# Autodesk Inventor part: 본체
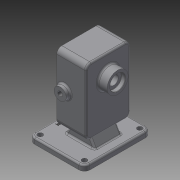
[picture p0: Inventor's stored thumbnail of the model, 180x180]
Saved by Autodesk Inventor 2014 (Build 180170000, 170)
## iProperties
Created: 2020-04
Part Number: 본체
Material: Generic
Document SubType Name: Modeling
Designer: kh
Density: 1 g/cm^3
Appearance: Default
Author: kh
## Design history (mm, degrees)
sketch "스케치1"
  geometry: L1 (-50, 60)-(50, 60); L2 (50, 60)-(50, -60); L3 (50, -60)-(-50, -60); L4 (-50, -60)-(-50, 60); L5 (-50, 60)-(50, -60); L6 (50, 60)-(-50, -60); 1 further point
  constraints: 12 end point, 2 midpoint, 2 parallel, 1 horizontal, 1 perpendicular
  dimensions: "d0" = 100 distance of L1.start L1.end; "d1" = 120 distance of L3.end L1.start
extrude "돌출1" new body sketch "스케치1" distance "d2" = 10; taper "d3" = 0 deg
node "작업 평면1"
sketch "스케치2"
  geometry: L1 (0, 60)-(-150, 60); L2 (-150, 20)-(-30, 20); L3 (-30, 20)-(-30, 100); L4 (-30, 100)-(-150, 100); L5 (-150, 100)-(-150, 20)
  constraints: 10 end point, 2 horizontal, 2 parallel, 1 midpoint, 1 perpendicular
  dimensions: "d5" = 150 distance of L1.end L1.start; "d6" = 80 distance of L4.end L2.start; "d7" = 120 distance of L2.start L2.end
extrude "돌출2" join sketch "스케치2" distance "d8" = 53; taper "d9" = 0 deg
sketch "스케치3"
  geometry: L1 (0, 60)-(90, 60); L2 (112, 60)-(68, 60); L3 (112, 84)-(68, 84); L4 (68, 36)-(112, 36); A1 r 24 centre (112, 60) between (112, 36) and (112, 84); A2 r 24 centre (68, 60) between (68, 84) and (68, 36); 1 further point
  constraints: 10 end point, 4 point on circle, 4 tangent, 2 centre point, 1 coincident, 1 collinear, 1 horizontal, 1 midpoint, 1 parallel
  dimensions: "d10" = 90 distance of L1.start L1.end; "d11" = 44 distance of L2.start L2.end; "d12" = 48 diameter of A2
extrude "돌출3" cut sketch "스케치3" distance "d13" = 29; taper "d14" = 0 deg
sketch "스케치4"
  geometry: L1 (68, 84)-(112, 84) reference; L2 (112, 36)-(68, 36) reference; C1 r 12.5 at (112, 60); C2 r 12.5 at (68, 60); A1 r 24 centre (68, 60) between (68, 84) and (68, 36) reference; A2 r 24 centre (112, 60) between (112, 36) and (112, 84) reference; 1 further point
  constraints: 2 centre point, 2 coincident
  dimensions: "d15" = 25 diameter of C1; "d16" = 25 diameter of C2
extrude "돌출4" cut sketch "스케치4" distance "d17" = 15; taper "d18" = 0 deg
chamfer "모따기1" distance "d19" = 1; stored, may be unused: second distance "d20" = 2, angle "d21" = 45 deg
sketch "스케치5"
  geometry: C1 r 12.5 at (-112, 60) reference; C2 r 19 at (-112, 60); 1 further point
  constraints: 1 centre point, 1 coincident
  dimensions: "d22" = 38 diameter of C2
extrude "돌출5" join sketch "스케치5" distance "d23" = 17; taper "d24" = 0 deg
sketch "스케치6"
  geometry: C1 r 19 at (0, 0) reference; C2 r 14 at (0, 0); 1 further point
  constraints: 1 centre point, 1 coincident
  dimensions: "d25" = 28 diameter of C2
extrude "돌출6" cut sketch "스케치6" distance "d26" = 7.3; taper "d27" = 0 deg
chamfer "모따기2" distance "d28" = 0.7; stored, may be unused: second distance "d29" = 2, angle "d30" = 30 deg
fillet "모깎기1" dims "d31" = 0.5
sketch "스케치7"
  geometry: C1 r 13.5 at (0, 0) reference; C2 r 8.5 at (0, 0); 1 further point
  constraints: 1 centre point, 1 coincident
  dimensions: "d32" = 17 diameter of C2
extrude "돌출7" cut sketch "스케치7" stored distance "d33" = 7.3; taper "d34" = 0 deg
sketch "스케치8"
  geometry: L1 (-53, 0)-(-53, 120) reference; L2 (17, -30)-(-83, -30) reference; C1 r 11 at (-39, 60); 2 further points
  constraints: 1 centre point, 1 coincident
  dimensions: "d35" = 14 distance from line of L1 point (-39, 60); "d36" = 90 distance from line of L2 point (-39, 60); "d37" = 22 diameter of C1
extrude "돌출8" join sketch "스케치8" distance "d38" = 8; taper "d39" = 0 deg
hole "구멍1" diameter "d42" = 8.917; stored, may be unused: countersink angle "d46" = 90 deg, drill point angle "d48" = 118 deg; dims "d40" = 10, "d41" = 10, "d43" = 6, "d44" = 4, "d45" = 2, "d47" = 8
fillet "모깎기2" dims "d49" = 10
fillet "모깎기3" dims "d50" = 9
fillet "모깎기4" dims "d51" = 3
sketch "스케치9"
  geometry: L1 (-50, -50)-(-50, 50) reference; L2 (-40, 60)-(40, 60) reference; L3 (50, 50)-(50, -50) reference; L4 (40, -60)-(-40, -60) reference; A1 r 10 centre (-40, -50) between (-50, -50) and (-40, -60) reference; A2 r 10 centre (-40, 50) between (-40, 60) and (-50, 50) reference; A3 r 10 centre (40, 50) between (50, 50) and (40, 60) reference; A4 r 10 centre (40, -50) between (40, -60) and (50, -50) reference; 1 further point
hole "구멍2" sketch "스케치9" at (-40, 50), (-40, -50), (40, -50), (40, 50) diameter "d52" = 9; stored, may be unused: countersink angle "d56" = 90 deg, drill point angle "d58" = 118 deg; dims "d53" = 6, "d54" = 4, "d55" = 2, "d57" = 8
sketch "스케치10"
  geometry: L1 (0, 60)-(90, 60); L2 (141, 91)-(39, 91); L3 (39, 91)-(39, 29); L4 (39, 29)-(141, 29); L5 (141, 29)-(141, 91); L6 (141, 91)-(39, 29); L7 (39, 91)-(141, 29); C1 r 8.5 at (112, 60) reference; C2 r 12.5 at (68, 60) reference; 8 further points
  constraints: 14 end point, 4 coincident, 4 point on line, 2 horizontal, 2 midpoint, 2 parallel, 2 symmetric about line, 1 perpendicular
  dimensions: "d59" = 90 distance of L1.start L1.end; "d60" = 62 distance of L4.end L2.start; "d61" = 102 distance of L3.end L4.end; "d62" = 44 distance of point (68, 29) point (112, 29); "d63" = 22 horizontal distance of L1.end point (112, 29)
hole "구멍3" sketch "스케치10" at (141, 91), (141, 29), (39, 29), (39, 91), (112, 91), (112, 29), (68, 91), (68, 29) diameter "d64" = 4.459; stored, may be unused: countersink angle "d68" = 90 deg, drill point angle "d70" = 118 deg; dims "d65" = 10, "d66" = 4, "d67" = 2, "d69" = 12
sketch "스케치11"
  geometry: L1 (-36.998, 20.739)-(-36.998, -20.739); L2 (-36.998, -20.739)-(-43.002, -20.739); L3 (-43.002, -20.739)-(-43.002, 20.739); L4 (-43.002, 20.739)-(-36.998, 20.739); L5 (-36.998, 20.739)-(-43.002, -20.739); L6 (-36.998, -20.739)-(-43.002, 20.739); L7 (-50, 50)-(-50, -50) reference; L8 (40, 60)-(-40, 60) reference; 2 further points
  constraints: 4 end point, 1 midpoint, 2 other
  dimensions: "d71" = 10 distance from line of point (-40, 0) L7; "d72" = 60 distance from line of point (-40, 0) L8
feature "엠보싱1" sketch "스케치11" dims "d0" = 100, "d1" = 120, "d10" = 90, "d11" = 44, "d12" = 48, "d73" = 0.5, "d74" = 0
sketch "스케치12"
  geometry: L1 (-33, 30)-(20, 30) reference; L2 (40, 10)-(-40, 10) reference; L3 (8.453, 30)-(20, 10); L4 (-21.453, 30)-(-33, 10); L5 (20, 150)-(-33, 150) reference; L6 (-6.5, 30)-(-6.5, 150); 1 further point
  constraints: 6 end point, 4 point on line, 2 midpoint, 1 other
  dimensions: "d75" = 60 deg angle of L2 L3; "d76" = 53 distance of L4.end L3.end
extrude "돌출9" join sketch "스케치12" stored distance "d77" = 48; taper "d78" = 0 deg
fillet "모깎기5" dims "d79" = 3
fillet "모깎기6" dims "d80" = 3
node "솔리드1"
mirror "대칭1"
node "투영된 루프1"
node "투영된 루프2"
node "투영된 루프3"
node "투영된 루프4"
other parameters: "d4" = -17
